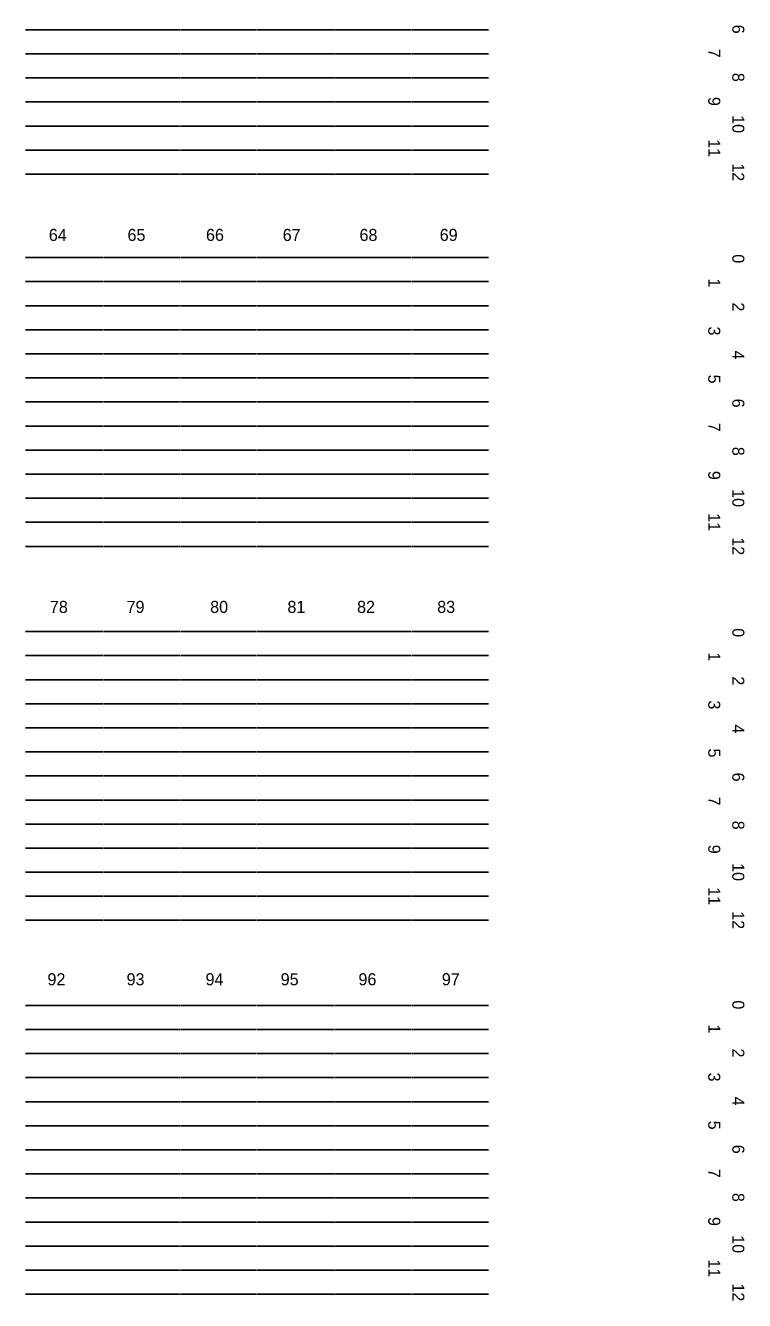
# Model space of a CAD drawing. Extents: x 11193 to 12507, y 10092 to 10555.
# Drawn here: x 11315.1 to 11444.6, y 10091.7 to 10321.2 of the extents above; entities that cross this region are included whole.
import ezdxf

# ---------------------------------------------------------------- set-up
doc = ezdxf.new("R2010")
doc.units = 0
doc.layers.add('Level 2', color=7, linetype='Continuous')

msp = doc.modelspace()

# ---------------------------------------------------------------- linework, layer by layer
at = {"layer": 'Level 2'}
for p, q in [((11315.14, 10320.47), (11329.11, 10320.47)), ((11329.21, 10320.47), (11342.99, 10320.47)), ((11343.1, 10320.47), (11356.66, 10320.47)), ((11356.77, 10320.47), (11370.74, 10320.47)), ((11370.85, 10320.47), (11384.63, 10320.47)), ((11384.74, 10320.47), (11398.48, 10320.47)), ((11315.14, 10316.14), (11329.11, 10316.14)), ((11329.21, 10316.14), (11342.99, 10316.14)), ((11343.1, 10316.14), (11356.66, 10316.14)), ((11356.77, 10316.14), (11370.74, 10316.14)), ((11370.85, 10316.14), (11384.63, 10316.14)), ((11384.74, 10316.14), (11398.48, 10316.14)), ((11315.14, 10311.81), (11329.11, 10311.81)), ((11329.21, 10311.81), (11342.99, 10311.81)), ((11343.1, 10311.81), (11356.66, 10311.81)), ((11356.77, 10311.81), (11370.74, 10311.81)), ((11370.85, 10311.81), (11384.63, 10311.81)), ((11384.74, 10311.81), (11398.48, 10311.81)), ((11315.14, 10307.48), (11329.11, 10307.48)), ((11329.21, 10307.48), (11342.99, 10307.48)), ((11343.1, 10307.48), (11356.66, 10307.48)), ((11356.77, 10307.48), (11370.74, 10307.48)), ((11370.85, 10307.48), (11384.63, 10307.48)), ((11384.74, 10307.48), (11398.48, 10307.48)), ((11315.14, 10303.14), (11329.11, 10303.14)), ((11329.21, 10303.14), (11342.99, 10303.14)), ((11343.1, 10303.14), (11356.66, 10303.14)), ((11356.77, 10303.14), (11370.74, 10303.14)), ((11370.85, 10303.14), (11384.63, 10303.14)), ((11384.74, 10303.14), (11398.48, 10303.14)), ((11315.14, 10298.81), (11329.11, 10298.81)), ((11329.21, 10298.81), (11342.99, 10298.81)), ((11343.1, 10298.81), (11356.66, 10298.81)), ((11356.77, 10298.81), (11370.74, 10298.81)), ((11370.85, 10298.81), (11384.63, 10298.81)), ((11384.74, 10298.81), (11398.48, 10298.81)), ((11315.14, 10294.48), (11329.11, 10294.48)), ((11329.21, 10294.48), (11342.99, 10294.48)), ((11343.1, 10294.48), (11356.66, 10294.48)), ((11356.77, 10294.48), (11370.74, 10294.48)), ((11370.85, 10294.48), (11384.63, 10294.48)), ((11384.74, 10294.48), (11398.48, 10294.48)), ((11315.14, 10279.46), (11329.13, 10279.46)), ((11329.23, 10279.46), (11343, 10279.46)), ((11343.1, 10279.46), (11356.68, 10279.46)), ((11356.78, 10279.46), (11370.76, 10279.46)), ((11370.86, 10279.46), (11384.64, 10279.46)), ((11384.75, 10279.46), (11398.48, 10279.46)), ((11315.14, 10275.13), (11329.13, 10275.13)), ((11329.23, 10275.13), (11343, 10275.13)), ((11343.1, 10275.13), (11356.68, 10275.13)), ((11356.78, 10275.13), (11370.76, 10275.13)), ((11370.86, 10275.13), (11384.64, 10275.13)), ((11384.75, 10275.13), (11398.48, 10275.13)), ((11315.14, 10270.79), (11329.13, 10270.79)), ((11329.23, 10270.79), (11343, 10270.79)), ((11343.1, 10270.79), (11356.68, 10270.79)), ((11356.78, 10270.79), (11370.76, 10270.79)), ((11370.86, 10270.79), (11384.64, 10270.79)), ((11384.75, 10270.79), (11398.48, 10270.79)), ((11315.14, 10266.46), (11329.13, 10266.46)), ((11329.23, 10266.46), (11343, 10266.46)), ((11343.1, 10266.46), (11356.68, 10266.46)), ((11356.78, 10266.46), (11370.76, 10266.46)), ((11370.86, 10266.46), (11384.64, 10266.46)), ((11384.75, 10266.46), (11398.48, 10266.46)), ((11315.14, 10262.13), (11329.13, 10262.13)), ((11329.23, 10262.13), (11343, 10262.13)), ((11343.1, 10262.13), (11356.68, 10262.13)), ((11356.78, 10262.13), (11370.76, 10262.13)), ((11370.86, 10262.13), (11384.64, 10262.13)), ((11384.75, 10262.13), (11398.48, 10262.13)), ((11315.14, 10257.8), (11329.13, 10257.8)), ((11329.23, 10257.8), (11343, 10257.8)), ((11343.1, 10257.8), (11356.68, 10257.8)), ((11356.78, 10257.8), (11370.76, 10257.8)), ((11370.86, 10257.8), (11384.64, 10257.8)), ((11384.75, 10257.8), (11398.48, 10257.8)), ((11315.14, 10253.47), (11329.13, 10253.47)), ((11329.23, 10253.47), (11343, 10253.47)), ((11343.1, 10253.47), (11356.68, 10253.47)), ((11356.78, 10253.47), (11370.76, 10253.47)), ((11370.86, 10253.47), (11384.64, 10253.47)), ((11384.75, 10253.47), (11398.48, 10253.47)), ((11315.14, 10249.13), (11329.13, 10249.13)), ((11329.23, 10249.13), (11343, 10249.13)), ((11343.1, 10249.13), (11356.68, 10249.13)), ((11356.78, 10249.13), (11370.76, 10249.13)), ((11370.86, 10249.13), (11384.64, 10249.13)), ((11384.75, 10249.13), (11398.48, 10249.13)), ((11315.14, 10244.8), (11329.13, 10244.8)), ((11329.23, 10244.8), (11343, 10244.8)), ((11343.1, 10244.8), (11356.68, 10244.8)), ((11356.78, 10244.8), (11370.76, 10244.8)), ((11370.86, 10244.8), (11384.64, 10244.8)), ((11384.75, 10244.8), (11398.48, 10244.8)), ((11315.14, 10240.47), (11329.13, 10240.47)), ((11329.23, 10240.47), (11343, 10240.47)), ((11343.1, 10240.47), (11356.68, 10240.47)), ((11356.78, 10240.47), (11370.76, 10240.47)), ((11370.86, 10240.47), (11384.64, 10240.47)), ((11384.75, 10240.47), (11398.48, 10240.47)), ((11315.14, 10236.14), (11329.13, 10236.14)), ((11329.23, 10236.14), (11343, 10236.14)), ((11343.1, 10236.14), (11356.68, 10236.14)), ((11356.78, 10236.14), (11370.76, 10236.14)), ((11370.86, 10236.14), (11384.64, 10236.14)), ((11384.75, 10236.14), (11398.48, 10236.14)), ((11315.14, 10231.81), (11329.13, 10231.81)), ((11329.23, 10231.81), (11343, 10231.81)), ((11343.1, 10231.81), (11356.68, 10231.81)), ((11356.78, 10231.81), (11370.76, 10231.81)), ((11370.86, 10231.81), (11384.64, 10231.81)), ((11384.75, 10231.81), (11398.48, 10231.81)), ((11315.14, 10227.47), (11329.13, 10227.47)), ((11329.23, 10227.47), (11343, 10227.47)), ((11343.1, 10227.47), (11356.68, 10227.47)), ((11356.78, 10227.47), (11370.76, 10227.47)), ((11370.86, 10227.47), (11384.64, 10227.47)), ((11384.75, 10227.47), (11398.48, 10227.47)), ((11315.14, 10212.14), (11329.13, 10212.14)), ((11329.23, 10212.14), (11343, 10212.14)), ((11343.1, 10212.14), (11356.68, 10212.14)), ((11356.78, 10212.14), (11370.76, 10212.14)), ((11370.86, 10212.14), (11384.64, 10212.14)), ((11384.75, 10212.14), (11398.48, 10212.14)), ((11315.14, 10207.81), (11329.13, 10207.81)), ((11329.23, 10207.81), (11343, 10207.81)), ((11343.1, 10207.81), (11356.68, 10207.81)), ((11356.78, 10207.81), (11370.76, 10207.81)), ((11370.86, 10207.81), (11384.64, 10207.81)), ((11384.75, 10207.81), (11398.48, 10207.81)), ((11315.14, 10203.48), (11329.13, 10203.48)), ((11329.23, 10203.48), (11343, 10203.48)), ((11343.1, 10203.48), (11356.68, 10203.48)), ((11356.78, 10203.48), (11370.76, 10203.48)), ((11370.86, 10203.48), (11384.64, 10203.48)), ((11384.75, 10203.48), (11398.48, 10203.48)), ((11315.14, 10199.14), (11329.13, 10199.14)), ((11329.23, 10199.14), (11343, 10199.14)), ((11343.1, 10199.14), (11356.68, 10199.14)), ((11356.78, 10199.14), (11370.76, 10199.14)), ((11370.86, 10199.14), (11384.64, 10199.14)), ((11384.75, 10199.14), (11398.48, 10199.14)), ((11315.14, 10194.81), (11329.13, 10194.81)), ((11329.23, 10194.81), (11343, 10194.81)), ((11343.1, 10194.81), (11356.68, 10194.81)), ((11356.78, 10194.81), (11370.76, 10194.81)), ((11370.86, 10194.81), (11384.64, 10194.81)), ((11384.75, 10194.81), (11398.48, 10194.81)), ((11315.14, 10190.48), (11329.13, 10190.48)), ((11329.23, 10190.48), (11343, 10190.48)), ((11343.1, 10190.48), (11356.68, 10190.48)), ((11356.78, 10190.48), (11370.76, 10190.48)), ((11370.86, 10190.48), (11384.64, 10190.48)), ((11384.75, 10190.48), (11398.48, 10190.48)), ((11315.14, 10186.15), (11329.13, 10186.15)), ((11329.23, 10186.15), (11343, 10186.15)), ((11343.1, 10186.15), (11356.68, 10186.15)), ((11356.78, 10186.15), (11370.76, 10186.15)), ((11370.86, 10186.15), (11384.64, 10186.15)), ((11384.75, 10186.15), (11398.48, 10186.15)), ((11315.14, 10181.82), (11329.13, 10181.82)), ((11329.23, 10181.82), (11343, 10181.82)), ((11343.1, 10181.82), (11356.68, 10181.82)), ((11356.78, 10181.82), (11370.76, 10181.82)), ((11370.86, 10181.82), (11384.64, 10181.82)), ((11384.75, 10181.82), (11398.48, 10181.82)), ((11315.14, 10177.48), (11329.13, 10177.48)), ((11329.23, 10177.48), (11343, 10177.48)), ((11343.1, 10177.48), (11356.68, 10177.48)), ((11356.78, 10177.48), (11370.76, 10177.48)), ((11370.86, 10177.48), (11384.64, 10177.48)), ((11384.75, 10177.48), (11398.48, 10177.48)), ((11315.14, 10173.15), (11329.13, 10173.15)), ((11329.23, 10173.15), (11343, 10173.15)), ((11343.1, 10173.15), (11356.68, 10173.15)), ((11356.78, 10173.15), (11370.76, 10173.15)), ((11370.86, 10173.15), (11384.64, 10173.15)), ((11384.75, 10173.15), (11398.48, 10173.15)), ((11315.14, 10168.82), (11329.13, 10168.82)), ((11329.23, 10168.82), (11343, 10168.82)), ((11343.1, 10168.82), (11356.68, 10168.82)), ((11356.78, 10168.82), (11370.76, 10168.82)), ((11370.86, 10168.82), (11384.64, 10168.82)), ((11384.75, 10168.82), (11398.48, 10168.82)), ((11315.14, 10164.49), (11329.13, 10164.49)), ((11329.23, 10164.49), (11343, 10164.49)), ((11343.1, 10164.49), (11356.68, 10164.49)), ((11356.78, 10164.49), (11370.76, 10164.49)), ((11370.86, 10164.49), (11384.64, 10164.49)), ((11384.75, 10164.49), (11398.48, 10164.49)), ((11315.14, 10160.16), (11329.13, 10160.16)), ((11329.23, 10160.16), (11343, 10160.16)), ((11343.1, 10160.16), (11356.68, 10160.16)), ((11356.78, 10160.16), (11370.76, 10160.16)), ((11370.86, 10160.16), (11384.64, 10160.16)), ((11384.75, 10160.16), (11398.48, 10160.16)), ((11315.14, 10144.83), (11329.11, 10144.83)), ((11329.21, 10144.83), (11342.99, 10144.83)), ((11343.1, 10144.83), (11356.66, 10144.83)), ((11356.77, 10144.83), (11370.74, 10144.83)), ((11370.85, 10144.83), (11384.63, 10144.83)), ((11384.74, 10144.83), (11398.48, 10144.83)), ((11315.14, 10140.5), (11329.11, 10140.5)), ((11329.21, 10140.5), (11342.99, 10140.5)), ((11343.1, 10140.5), (11356.66, 10140.5)), ((11356.77, 10140.5), (11370.74, 10140.5)), ((11370.85, 10140.5), (11384.63, 10140.5)), ((11384.74, 10140.5), (11398.48, 10140.5)), ((11315.14, 10136.17), (11329.11, 10136.17)), ((11329.21, 10136.17), (11342.99, 10136.17)), ((11343.1, 10136.17), (11356.66, 10136.17)), ((11356.77, 10136.17), (11370.74, 10136.17)), ((11370.85, 10136.17), (11384.63, 10136.17)), ((11384.74, 10136.17), (11398.48, 10136.17)), ((11315.14, 10131.84), (11329.11, 10131.84)), ((11329.21, 10131.84), (11342.99, 10131.84)), ((11343.1, 10131.84), (11356.66, 10131.84)), ((11356.77, 10131.84), (11370.74, 10131.84)), ((11370.85, 10131.84), (11384.63, 10131.84)), ((11384.74, 10131.84), (11398.48, 10131.84)), ((11315.14, 10127.51), (11329.11, 10127.51)), ((11329.21, 10127.51), (11342.99, 10127.51)), ((11343.1, 10127.51), (11356.66, 10127.51)), ((11356.77, 10127.51), (11370.74, 10127.51)), ((11370.85, 10127.51), (11384.63, 10127.51)), ((11384.74, 10127.51), (11398.48, 10127.51)), ((11315.14, 10123.17), (11329.11, 10123.17)), ((11329.21, 10123.17), (11342.99, 10123.17)), ((11343.1, 10123.17), (11356.66, 10123.17)), ((11356.77, 10123.17), (11370.74, 10123.17)), ((11370.85, 10123.17), (11384.63, 10123.17)), ((11384.74, 10123.17), (11398.48, 10123.17)), ((11315.14, 10118.84), (11329.11, 10118.84)), ((11329.21, 10118.84), (11342.99, 10118.84)), ((11343.1, 10118.84), (11356.66, 10118.84)), ((11356.77, 10118.84), (11370.74, 10118.84)), ((11370.85, 10118.84), (11384.63, 10118.84)), ((11384.74, 10118.84), (11398.48, 10118.84)), ((11315.14, 10114.51), (11329.11, 10114.51)), ((11329.21, 10114.51), (11342.99, 10114.51)), ((11343.1, 10114.51), (11356.66, 10114.51)), ((11356.77, 10114.51), (11370.74, 10114.51)), ((11370.85, 10114.51), (11384.63, 10114.51)), ((11384.74, 10114.51), (11398.48, 10114.51)), ((11315.14, 10110.18), (11329.11, 10110.18)), ((11329.21, 10110.18), (11342.99, 10110.18)), ((11343.1, 10110.18), (11356.66, 10110.18)), ((11356.77, 10110.18), (11370.74, 10110.18)), ((11370.85, 10110.18), (11384.63, 10110.18)), ((11384.74, 10110.18), (11398.48, 10110.18)), ((11315.14, 10105.85), (11329.11, 10105.85)), ((11329.21, 10105.85), (11342.99, 10105.85)), ((11343.1, 10105.85), (11356.66, 10105.85)), ((11356.77, 10105.85), (11370.74, 10105.85)), ((11370.85, 10105.85), (11384.63, 10105.85)), ((11384.74, 10105.85), (11398.48, 10105.85)), ((11315.14, 10101.51), (11329.11, 10101.51)), ((11329.21, 10101.51), (11342.99, 10101.51)), ((11343.1, 10101.51), (11356.66, 10101.51)), ((11356.77, 10101.51), (11370.74, 10101.51)), ((11370.85, 10101.51), (11384.63, 10101.51)), ((11384.74, 10101.51), (11398.48, 10101.51)), ((11315.14, 10097.18), (11329.11, 10097.18)), ((11329.21, 10097.18), (11342.99, 10097.18)), ((11343.1, 10097.18), (11356.66, 10097.18)), ((11356.77, 10097.18), (11370.74, 10097.18)), ((11370.85, 10097.18), (11384.63, 10097.18)), ((11384.74, 10097.18), (11398.48, 10097.18)), ((11315.14, 10092.85), (11329.11, 10092.85)), ((11329.21, 10092.85), (11342.99, 10092.85)), ((11343.1, 10092.85), (11356.66, 10092.85)), ((11356.77, 10092.85), (11370.74, 10092.85)), ((11370.85, 10092.85), (11384.63, 10092.85)), ((11384.74, 10092.85), (11398.48, 10092.85))]:
    msp.add_line(p, q, dxfattribs=at)

# ---------------------------------------------------------------- texts
for s, height, p in [('6', 2.17, (11442.4, 10321.39)), ('7', 2.17, (11438.07, 10317.06)), ('8', 2.17, (11442.4, 10312.72)), ('9', 2.17, (11438.07, 10308.39)), ('10', 2.166, (11442.4, 10305.1)), ('11', 2.166, (11438.07, 10300.76)), ('12', 2.166, (11442.4, 10296.43)), ('0', 2.17, (11442.4, 10280.06)), ('1', 2.17, (11438.07, 10275.73)), ('2', 2.17, (11442.4, 10271.4)), ('3', 2.17, (11438.07, 10267.06)), ('4', 2.17, (11442.4, 10262.73)), ('5', 2.17, (11438.07, 10258.4)), ('6', 2.17, (11442.4, 10254.07)), ('7', 2.17, (11438.07, 10249.74)), ('8', 2.17, (11442.4, 10245.4)), ('9', 2.17, (11438.07, 10241.07)), ('10', 2.166, (11442.4, 10237.78)), ('11', 2.166, (11438.07, 10233.44)), ('12', 2.166, (11442.4, 10229.11)), ('0', 2.17, (11442.4, 10212.75)), ('1', 2.17, (11438.07, 10208.41)), ('2', 2.17, (11442.4, 10204.08)), ('3', 2.17, (11438.07, 10199.75)), ('4', 2.17, (11442.4, 10195.42)), ('5', 2.17, (11438.07, 10191.09)), ('6', 2.17, (11442.4, 10186.75)), ('7', 2.17, (11438.07, 10182.42)), ('8', 2.17, (11442.4, 10178.09)), ('9', 2.17, (11438.07, 10173.76)), ('10', 2.166, (11442.4, 10170.46)), ('11', 2.166, (11438.07, 10166.13)), ('12', 2.166, (11442.4, 10161.8)), ('0', 2.17, (11442.4, 10145.75)), ('1', 2.17, (11438.07, 10141.42)), ('2', 2.17, (11442.4, 10137.09)), ('3', 2.17, (11438.07, 10132.75)), ('4', 2.17, (11442.4, 10128.42)), ('5', 2.17, (11438.07, 10124.09)), ('6', 2.17, (11442.4, 10119.76)), ('7', 2.17, (11438.07, 10115.43)), ('8', 2.17, (11442.4, 10111.09)), ('9', 2.17, (11438.07, 10106.76)), ('10', 2.166, (11442.4, 10103.47)), ('11', 2.166, (11438.07, 10099.13)), ('12', 2.166, (11442.4, 10094.8))]:
    msp.add_text(s, height=height, rotation=270, dxfattribs=at).set_placement(p)
for s, p in [('64', (11319.34, 10282.46)), ('65', (11333.51, 10282.46)), ('66', (11347.64, 10282.46)), ('67', (11361.45, 10282.46)), ('68', (11375.28, 10282.46)), ('69', (11389.72, 10282.46)), ('78', (11319.53, 10215.5)), ('79', (11333.34, 10215.5)), ('80', (11348.39, 10215.5)), ('81', (11362.3, 10215.5)), ('82', (11374.84, 10215.5)), ('83', (11389.27, 10215.5)), ('92', (11319.1, 10148.46)), ('93', (11333.34, 10148.46)), ('94', (11347.56, 10148.46)), ('95', (11361.09, 10148.46)), ('96', (11375.09, 10148.46)), ('97', (11390.1, 10148.46))]:
    msp.add_text(s, height=2.17, dxfattribs=at).set_placement(p)

doc.saveas('drawing.dxf')
